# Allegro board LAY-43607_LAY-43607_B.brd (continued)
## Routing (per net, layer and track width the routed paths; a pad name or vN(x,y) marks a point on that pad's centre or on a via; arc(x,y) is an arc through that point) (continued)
QSG3_MDI3_N: length 55
  TOP w0.105: U123.D32 v2(40.94,79.95)
  L3_INT_1 w0.094: P2.2 35.29,107.25 35.54,106.99 36.89,106.99 37.85,106.03 37.85,105.67 37.94,105.57 37.95,105.57 38.04,105.48 38.04,105.29 37.95,105.2 37.94,105.2 37.85,105.1 37.85,104.91 37.94,104.82 37.95,104.82 38.04,104.73 38.04,104.54 37.95,104.44 37.94,104.44 37.85,104.35 37.85,102.45 37.3,101.9 27.31,101.9 22.99,97.58 22.99,89.73 26.33,86.39 33.21,86.39 39.65,79.95 v2(40.94,79.95)
QSG3_MDI3_P: length 55
  TOP w0.105: v2(39.07,78.77) 39.01,78.84 39.01,79.18 38.97,79.22 38.97,79.4 39.29,79.71 39.32,79.71 39.55,79.95 U123.D33
  L3_INT_1 w0.094: v2(39.07,78.77) 39.02,78.82 39.02,80.05 33.06,86.02 26.17,86.02 22.62,89.58 22.62,97.73 27.15,102.27 37.14,102.27 37.48,102.6 37.48,105.86 36.72,106.62 36.01,106.62 35.67,106.28 35.67,105.98 P2.8
QSGM_REXT: length 4.5
  TOP w0.137: R662.1 41.64,85.74 41.83,85.54 41.83,84.07 41.97,83.94 U123.A8
QSGM_REXT0: length 3.5
  TOP w0.137: U123.D17 46,70.19 46,69.69 R663.1
QSGM_REXT1: length 3.6
  TOP w0.137: R663.2 46.65,70.54 45.25,71.95 U123.D18
QSGPHY1_INT_B: length 66.7
  TOP w0.137: v3(71.82,44.59) 71.42,44.99 U14.F15 ; v2(31.84,71.21) R660.2
  L3_INT_1 w0.107: v2(61.81,67.38) 61.81,67.37 59.02,67.37 57.42,68.98 55.33,68.98 54.81,69.5 51.74,69.5 51.22,70.02 44.91,70.02 44.41,69.52 43.88,69.52 43.83,69.5 43.75,69.48 42.78,69.48 42.7,69.5 42.65,69.52 41.93,69.52 41.53,69.92 33.13,69.92 v2(31.84,71.21)
  BOTTOM w0.137: v2(61.81,67.38) 63.6,67.38 64.15,66.82 64.15,61.94 64.55,61.55 64.55,59.88 63.95,59.28 63.95,56.19 64.49,55.66 64.49,46.03 65.06,45.46 71.33,45.46 71.82,44.97 v3(71.82,44.59) ; R660.2 v2(31.84,71.21)
QSGPHY1_RST_B: length 26.6
  TOP w0.105: 35.85,74.97 U123.B5
  TOP w0.137: 35.85,74.97 34.93,74.97 R654.1 33.86,76.58 v2(33.69,76.75)
  BOTTOM w0.137: U62.4 47.04,65.52 46.84,65.72 46.84,67.66 44.58,69.92 35.77,69.92 34.93,70.75 34.93,75.51 v2(33.69,76.75)
QSGPHY_REFCLK_125M_N: length 30.3
  TOP w0.124: C850.1 38.79,67.58 38.79,67.18 38.26,66.65 37.7,66.65 34.67,69.68 31.92,69.68 30.65,70.96 20.88,70.96 19.53,69.6 19.53,67.31 20.58,66.26 20.83,66.26 20.95,66.39 20.95,66.39 21.08,66.51 21.33,66.51 21.45,66.39 21.45,66.39 21.57,66.26 21.82,66.26 21.95,66.39 21.95,66.39 22.07,66.51 22.32,66.51 22.45,66.39 22.45,66.39 22.57,66.26 23.99,66.26 U50.13
QSGPHY_REFCLK_125M_P: length 30.4
  TOP w0.124: U50.14 23.97,65.94 20.44,65.94 19.21,67.18 19.21,69.73 20.75,71.28 30.78,71.28 32.05,70 34.8,70 37.83,66.97 38.13,66.97 38.47,67.31 38.47,67.58 C849.1
QSPI_A_CS0: length 62.8
  TOP w0.137: U532.7 v2(105.78,25.44) 107.33,26.99 109.38,26.99 110.5,28.11 v2(110.5,29.05) ; v3(74.2,50.96) 73.83,50.96 73.83,50.96 73.39,50.96 73.29,50.86 73.29,50.86 U14.D8
  L3_INT_1 w0.107: v3(74.2,50.96) 80.43,50.96 80.65,50.74 81.47,50.74 84.64,47.57 86.99,47.57 87.22,47.35 90.94,47.35 92.35,45.93 94.48,45.93 95.92,44.5 95.92,42.95 97.27,41.6 98.79,41.6 102.93,37.46 104,37.46 105.12,36.34 105.12,34.76 106.13,33.75 106.13,33 106.39,32.75 106.39,30.42 107.76,29.05 v2(110.5,29.05)
  BOTTOM w0.137: R809.2 105.1,25.16 105.38,25.44 v2(105.78,25.44)
QSPI_A_DATA0: length 59.3
  TOP w0.137: U14.D11 73.03,48.2 v3(73.43,48.59) ; v2(109.43,27.63) 109.89,28.08 109.89,30.09 111.6,31.79 U532.15
  L3_INT_1 w0.107: v2(109.43,27.63) 108.02,27.63 105.56,30.08 105.56,32.29 102.47,35.38 102.21,35.38 99.58,38.01 99.48,38.01 98.08,39.41 97.95,39.41 97.67,39.69 97.67,40 95.1,42.58 95.1,44.15 94.12,45.12 92,45.12 90.6,46.52 86.88,46.52 86.65,46.75 84.37,46.75 81.26,49.87 80.27,49.87 79.68,49.28 79.21,49.28 79.1,49.38 79.1,49.8 79,49.9 78.78,49.9 78.68,49.8 78.68,49.08 78.55,48.95 77.02,48.95 76.92,49.06 76.92,49.81 76.81,49.92 76.6,49.92 76.49,49.81 76.49,49.06 76.38,48.95 76.17,48.95 76.06,49.06 76.06,49.81 75.96,49.92 75.74,49.92 75.64,49.81 75.64,49.06 75.53,48.95 74.38,48.95 74.37,48.95 74.08,48.95 74.08,48.95 73.78,48.95 v3(73.43,48.59)
QSPI_A_DATA1: length 59.5
  TOP w0.137: v2(109.28,25.98) 107.82,24.51 107.24,24.51 106.9,24.17 U532.8 ; U14.C12 v3(74.22,47.8)
  L3_INT_1 w0.107: v2(109.28,25.98) 109.28,26.75 108.67,27.37 107.69,27.37 104.15,30.91 104.15,32.07 100.03,36.19 99.78,36.19 97.85,38.12 97.7,38.12 97.29,37.72 97.14,37.72 96.99,37.87 96.99,38.02 97.39,38.42 97.39,38.57 96.98,38.98 96.8,38.98 95.74,40.04 95.74,41.35 94.68,42.41 94.68,43.6 94.13,44.16 93.98,44.16 92.99,43.17 92.83,43.17 92.68,43.32 92.68,43.47 93.64,44.43 93.64,44.64 93.48,44.81 93.1,44.81 92.68,44.39 92.15,44.39 90.43,46.11 86.71,46.11 86.54,46.28 84.36,46.28 82.25,48.4 80.61,48.4 80.13,47.93 74.71,47.93 74.58,47.8 v3(74.22,47.8)
QSPI_A_DATA2: length 60.8
  TOP w0.137: R810.2 U532.9 110.68,24.17 v2(109.88,23.37) ; U14.D13 73.42,46.99 v3(73.43,46.99)
  L3_INT_1 w0.107: v3(73.43,46.99) 73.83,47.4 74.33,47.4 74.44,47.5 82.71,47.5 84.26,45.95 84.26,45.63 84.53,45.35 85.89,45.35 85.99,45.46 85.99,45.61 86.1,45.72 86.31,45.72 86.42,45.61 86.42,45.46 86.53,45.35 87.25,45.35 87.36,45.46 87.36,45.63 87.46,45.74 87.68,45.74 87.78,45.63 87.78,45.46 87.89,45.35 88.1,45.35 88.21,45.46 88.21,45.63 88.32,45.74 88.53,45.74 88.64,45.63 88.64,45.46 88.74,45.35 89.89,45.35 93.16,42.09 93.31,42.09 93.67,42.45 93.82,42.45 93.97,42.3 93.97,42.15 93.61,41.79 93.61,41.64 95.82,39.43 95.82,37.23 96.43,36.62 98.06,36.62 98.22,36.45 98.37,36.45 98.52,36.6 98.67,36.6 98.82,36.45 98.82,36.3 98.68,36.15 98.68,36 99.5,35.17 100.47,35.17 102.29,33.35 102.29,33.2 102.03,32.93 102.03,32.78 102.18,32.63 102.33,32.63 102.6,32.89 102.75,32.89 102.9,32.74 102.9,32.59 102.63,32.33 102.63,32.18 102.79,32.03 102.94,32.03 103.2,32.29 103.35,32.29 103.64,32 103.64,30.94 107.54,27.04 108.54,27.04 108.85,26.73 108.85,25.73 109.88,24.7 v2(109.88,23.37)
QSPI_A_DATA3: length 60.3
  TOP w0.137: v2(101.41,33.4) 101.74,33.06 U532.1 ; v3(74.23,46.99) 74.22,46.99 U14.C13
  L3_INT_1 w0.107: v2(101.41,33.4) 101.12,33.69 101.12,34.08 100.38,34.82 99.93,34.82 99.83,34.72 99.83,34.63 99.72,34.52 99.51,34.52 99.4,34.63 99.4,34.72 99.29,34.82 99.08,34.82 98.97,34.72 98.97,34.63 98.87,34.52 98.65,34.52 98.55,34.63 98.55,34.72 98.44,34.82 98.2,34.82 96.82,36.2 96.42,36.2 95.97,35.75 95.74,35.75 95.63,35.86 95.63,36.09 95.53,36.2 95.31,36.2 95.21,36.09 95.21,35.86 95.1,35.75 94.89,35.75 94.78,35.86 94.78,36.09 94.67,36.2 94.46,36.2 94.35,36.09 94.35,35.86 94.25,35.75 93.83,35.75 93.49,36.1 93.49,36.42 93.66,36.59 95.22,36.59 95.32,36.69 95.32,38.06 95.22,38.17 93.7,38.17 93.59,38.28 93.59,38.49 93.7,38.6 95.22,38.6 95.32,38.7 95.32,39.34 95.08,39.59 94.93,39.59 94.37,39.03 94.16,39.03 94.05,39.13 94.05,39.33 94.62,39.9 94.62,40.05 94.47,40.19 94.32,40.19 93.87,39.74 93.72,39.74 93.61,39.85 93.61,40.08 94.02,40.49 94.02,40.64 90.32,44.34 89.98,44.34 89.88,44.24 89.88,43.97 89.77,43.86 89.56,43.86 89.45,43.97 89.45,44.92 89.34,45.03 89.15,45.03 89.02,44.9 89.02,43.97 88.92,43.86 88.7,43.86 88.6,43.97 88.6,44.24 88.49,44.34 88.28,44.34 88.17,44.24 88.17,43.97 88.06,43.86 87.85,43.86 87.74,43.97 87.74,44.24 87.64,44.34 87.4,44.34 87.3,44.45 87.3,44.94 87.19,45.04 86.98,45.04 86.87,44.94 86.87,44.45 86.76,44.34 86.55,44.34 86.44,44.45 86.44,44.94 86.34,45.04 86.12,45.04 86.02,44.94 86.02,44.45 85.74,44.17 85.13,44.17 85.02,44.28 85.02,44.38 84.92,44.49 84.7,44.49 84.5,44.28 84.35,44.28 83.96,44.66 83.96,44.81 84.22,45.08 84.22,45.23 83.95,45.5 83.95,45.82 83.78,45.99 83.63,45.99 83.22,45.58 83.07,45.58 82.92,45.73 82.92,45.88 83.04,46 83.04,46.15 82.9,46.28 82.9,46.69 82.67,46.92 82.67,46.95 82.43,47.19 75.94,47.19 75,46.25 74.67,46.25 74.48,46.44 74.48,46.74 v3(74.23,46.99)
  BOTTOM w0.137: v2(101.41,33.4) 101.74,33.06 102.01,33.06 102.16,32.91 R811.2
QSPI_A_SCK: length 59.7
  TOP w0.137: U532.16 111.57,33.06 109.41,30.9 v2(109.41,28.57) ; v3(74.23,50.19) 73.83,49.8 U14.C9
  L3_INT_1 w0.107: v3(74.23,50.19) 74.62,50.59 80.36,50.59 80.56,50.4 81.26,50.4 82.12,49.53 82.14,49.53 84.51,47.16 86.82,47.16 87.05,46.94 90.74,46.94 92.23,45.45 94.38,45.45 95.51,44.32 95.51,42.75 97.12,41.14 97.73,41.14 101.28,37.59 101.71,37.59 102.93,36.37 103.31,36.37 104.05,35.63 104.05,34.46 105.97,32.53 105.97,30.25 108.12,28.11 109.56,28.11 109.83,27.84 109.83,26.74 109.98,26.6 110.4,26.6 110.53,26.73 110.53,28.05 110.02,28.57 v2(109.41,28.57)
R_LED_ASLEEP: length 5.2
  TOP w0.137: R191.1 94.09,47.21 Q4.3
R_USB1_LED: length 1.2
  TOP w0.137: R244.2 114.2,99.33 D4.A
R_USB2_LED: length 1.4
  TOP w0.137: D508.A 107.29,99.06 107.26,99.03 106.54,99.03
RESET_MCU_B: length 66.4
  TOP w0.137: R939.2 79.33,83.3 79.48,83.45 86.07,83.45 v2(86.37,83.15)
  L3_INT_1 w0.107: v2(97.05,73.03) 95.09,73.03 94.05,71.99 84.35,71.99 82.12,69.76 76.08,69.76 75.71,70.14 70.87,70.14 v2(69.89,69.16) ; v2(98.53,77.35) 91.45,77.35 86.37,82.43 v2(86.37,83.15)
  BOTTOM w0.137: U547.2 100.01,67.45 100.01,68.65 99.5,69.16 98.42,69.16 97.05,70.53 v2(97.05,73.03) 97.05,73.55 98.3,74.8 98.3,76.01 98.53,76.24 v2(98.53,77.35) ; R938.2 v2(69.89,69.16)
RESET_REQ_B: length 38.1
  TOP w0.137: R298.2 120.89,16.86 v2(120.89,17.72) ; v2(130.57,18.58) 131.17,19.19 131.17,37.96 131.4,38.2 131.4,41.73 J14.1
  BOTTOM w0.137: v2(120.89,17.72) U534.2 120.89,16.12 125.43,16.12 127.59,18.28 130.26,18.28 v2(130.57,18.58)
RST_I2CMUX_B: length 7.6
  TOP w0.137: v2(87.94,84.65) 87.94,84.69 88.22,84.97 U525.3
  BOTTOM w0.137: v2(87.94,84.65) 87.86,84.73 R758.2 87.35,85.56 86.28,86.63 86.28,87.51 v2(87.41,88.64) U527.4
RST_MEM_B: length 111.1
  TOP w0.137: U15.P1 89.35,7.42 88.63,7.42 86.89,5.67 v2(86.89,5.64)
  L3_INT_1 w0.107: v2(86.89,5.64) 87.55,4.98 89.33,4.98 90.09,5.74 91.06,5.74 91.08,5.72 97.09,5.72 101.71,10.35 v2(101.71,17.59) ; v1(78.16,7.71) 77.78,7.32 71.32,7.32 70.9,7.75 69.19,7.75 68.77,7.32 68.12,7.32 67.86,7.58 67.86,7.87 67.64,8.09 67.06,8.09 v1(66.68,7.71) 66.22,7.25 66.22,5.99 64.36,4.13 58.91,4.13 57.5,5.55 57.5,5.66 57.11,6.04 56.87,6.04 v1(55.2,7.71) 54.82,8.09 44.1,8.09 v1(43.72,7.71) ; v2(115.97,26.36) v2(115.97,16.44)
  L4_INT_2 w0.107: v1(78.16,7.71) 78.16,6.67 78.55,6.29 78.55,5.98 79.23,5.3 81.48,5.3 82.28,6.11 84.02,6.11 84.4,6.49 84.83,6.49 85.8,5.53 86.77,5.53 v2(86.89,5.64)
  BOTTOM w0.137: v2(115.97,16.44) 115.55,16.02 R558.2 103.69,17.59 v2(101.71,17.59) ; U114.4 121.72,26.41 121.19,26.93 119.76,26.93 119.2,26.36 v2(115.97,26.36)
RSV_IO: length 9.2
  TOP w0.137: R824.1 52.33,62.01 52.33,58.86 v2(53.22,57.96) ; U14.AF3 v2(55.02,55)
  L4_INT_2 w0.107: v2(53.22,57.96) 53.22,56.8 v2(55.02,55)
SCAN_MODE: length 20.3
  TOP w0.137: v3(69.42,41.4) U14.H19
  BOTTOM w0.137: v3(69.42,41.4) 69.02,41.79 69.02,44.76 69.26,45 71.15,45 71.4,44.75 71.4,44.49 71.67,44.22 71.98,44.22 73.07,45.31 75.32,45.31 76.55,44.08 76.55,44.08 77.08,43.55 81.55,43.55 R160.2
SD1_IMP_CAL_RX: length 2.3
  TOP w0.137: v2(59.82,48.6) U14.Y11
  BOTTOM w0.137: v2(59.82,48.6) 59.43,48.99 59.43,49.69 R260.1
SD1_IMP_CAL_TX: length 16.4
  TOP w0.137: v2(59.02,52.6) U14.AA6 ; v2(46.34,54.39) R258.1
  L3_INT_1 w0.107: v2(46.34,54.39) 47.75,54.39 48.8,55.44 51.63,55.44 54.06,53.01 56.78,53.01 57.04,53.27 57.04,53.55 57.26,53.78 57.98,53.78 59.02,52.74 v2(59.02,52.6)
SD1_REFCLK2_N: length 40.6
  TOP w0.124: R792.2 24.33,60.17 24.59,59.91 24.59,59.55 24.77,59.38 24.77,59.2 24.69,59.13 24.69,58.95 24.87,58.78 25.05,58.78 25.12,58.85 25.29,58.85 26.23,57.91 35.43,57.91 36.65,56.69 38.2,56.69 40.01,58.5 40.29,58.5 v2(40.58,58.21) ; U14.AB8 v2(58.22,51)
  BOTTOM w0.124: v2(58.22,51) 58.17,51.05 55.57,51.05 53.18,53.43 48.87,53.43 47.12,55.18 45.1,55.18 41.78,58.5 40.87,58.5 v2(40.58,58.21)
SD1_REFCLK2_P: length 40.6
  TOP w0.124: U14.AA8 v2(59.02,51) ; v2(40.58,59.12) 40.28,58.82 39.87,58.82 38.07,57.01 36.78,57.01 35.56,58.23 26.36,58.23 24.91,59.69 24.91,59.91 R791.2
  BOTTOM w0.124: v2(59.02,51) 58.78,51 58.39,51.39 58.06,51.39 58.04,51.37 55.7,51.37 53.31,53.75 49,53.75 47.26,55.5 45.23,55.5 41.91,58.82 40.87,58.82 v2(40.58,59.12)
SD1_RX2_N: length 25.6
  TOP w0.124: C1583.1 42.09,48.77 40.93,48.77 40.26,49.44 40.26,54.86 41.53,56.13 41.53,60.17 41.16,60.54 41.16,71.6 arc(41.12,71.77) 41.03,71.91 U123.D13
SD1_RX2_P: length 25.6
  TOP w0.124: C1582.1 42.09,49.09 41.07,49.09 40.58,49.57 40.58,54.73 41.85,55.99 41.85,60.3 41.48,60.67 41.48,69.39 arc(41.5,69.46) 41.57,69.49 arc(41.64,69.52) 41.67,69.59 41.67,69.9 arc(41.64,69.97) 41.57,70 arc(41.5,70.02) 41.48,70.09 41.48,70.4 arc(41.5,70.47) 41.57,70.5 arc(41.65,70.53) 41.69,70.61 41.69,70.89 arc(41.65,70.97) 41.57,71.01 arc(41.5,71.04) 41.48,71.1 41.48,71.6 arc(41.51,71.77) 41.61,71.91 U123.D14
SD1_TX2_N: length 34.4
  TOP w0.124: U14.AE10 v2(55.82,48.6)
  BOTTOM w0.124: v1(42.82,68.88) 42.99,68.88 arc(43.07,68.84) 43.11,68.77 43.11,67.62 arc(42.93,67.18) 42.49,67 41.72,67 arc(41.43,66.94) 41.18,66.78 39.85,65.44 arc(39.62,65.1) 39.54,64.7 39.54,58.29 arc(39.61,57.93) 39.82,57.62 44.64,52.79 arc(45.63,52.13) 46.79,51.9 49.95,51.9 arc(50.37,51.82) 50.73,51.58 52.61,49.69 arc(53.07,49.39) 53.61,49.28 55.87,49.28 arc(56.01,49.22) 56.06,49.08 56.06,48.94 arc(56.05,48.84) 55.99,48.76 v2(55.82,48.6)
SD1_TX2_P: length 34.4
  TOP w0.124: U14.AD10 v2(56.62,48.6)
  BOTTOM w0.124: v2(56.62,48.6) 56.46,48.76 arc(56.4,48.84) 56.38,48.94 56.38,49.08 arc(56.23,49.45) 55.87,49.6 53.61,49.6 arc(53.19,49.68) 52.84,49.92 50.95,51.81 arc(50.49,52.11) 49.95,52.22 46.79,52.22 arc(45.75,52.43) 44.87,53.02 40.04,57.84 arc(39.91,58.05) 39.86,58.29 39.86,64.7 arc(39.91,64.98) 40.07,65.21 41.41,66.55 arc(41.55,66.65) 41.72,66.68 42.49,66.68 arc(43.15,66.95) 43.43,67.62 43.43,68.75 arc(43.46,68.84) 43.55,68.88 v1(43.71,68.88)
SD2_IMP_CAL_RX: length 4.8
  TOP w0.137: v2(59.82,47.8) U14.Y12
  BOTTOM w0.137: R261.1 61.64,45.43 61.83,45.62 61.83,47.16 61.6,47.39 60.23,47.39 v2(59.82,47.8)
SD2_IMP_CAL_TX: length 25.7
  TOP w0.137: R259.1 v2(44.56,48.38) ; v2(59.82,40.6) U14.Y20
  L3_INT_1 w0.107: v2(44.56,48.38) 43.74,47.56 43.74,44.84 44.56,44.02 44.56,41.61 46.79,39.39 59.16,39.39 59.44,39.67 59.44,39.95 59.82,40.34 v2(59.82,40.6)
SD2_REFCLK1_N: length 36.3
  TOP w0.124: v2(33.93,65.71) 33.66,65.98 32.92,65.98 R784.2 ; U14.AE13 v2(55.82,47)
  BOTTOM w0.124: v2(55.82,47) 55.75,47.07 55.41,47.07 arc(55.34,47.04) 55.3,46.97 arc(55.25,46.9) 55.18,46.88 54.91,46.88 arc(54.84,46.9) 54.79,46.97 arc(54.75,47.04) 54.68,47.07 52.83,47.07 50.82,49.08 50.82,50.07 50.24,50.65 45.09,50.65 37.63,58.11 37.63,58.22 37.63,62.83 35.37,65.09 35.19,65.09 35.01,64.91 34.83,64.91 34.66,65.09 34.66,65.26 34.84,65.44 34.84,65.62 34.45,66.01 34.22,66.01 v2(33.93,65.71)
SD2_REFCLK1_P: length 36.3
  TOP w0.124: v2(33.93,66.62) 33.6,66.3 32.77,66.3 R783.2 ; U14.AD13 v2(56.62,47)
  BOTTOM w0.124: v2(56.62,47) 56.23,47.39 52.97,47.39 51.14,49.21 51.14,50.2 50.37,50.97 45.22,50.97 37.95,58.24 37.95,58.36 37.95,62.97 34.59,66.33 34.22,66.33 v2(33.93,66.62)
SD2_REFCLK2_N: length 41
  TOP w0.124: v2(36.07,59.94) 36.25,60.12 36.25,61.4 35.61,62.04 34.13,62.04 R790.2
  TOP w0.137: v3(58.22,42.2) U14.AB19
  L4_INT_2 w0.094: v2(36.88,52.49) 36.71,52.66 36.4,52.66 36.09,52.97 36.09,54.12 36.21,54.23 36.21,59.8 v2(36.07,59.94)
  BOTTOM w0.124: v3(58.22,42.2) 57.98,42.44 57.74,42.44 57.59,42.59 55.99,42.59 55.19,43.39 50.34,43.39 49.64,42.68 44.45,42.68 38.87,48.26 38.87,51.25 37.5,52.62 37.01,52.62 v2(36.88,52.49)
SD2_REFCLK2_P: length 41
  TOP w0.124: R789.2 34.13,62.36 35.74,62.36 36.57,61.54 36.57,60.09 v2(36.78,59.88)
  TOP w0.137: v3(58.22,43) U14.AB18
  L4_INT_2 w0.094: v2(36.78,59.88) 36.58,59.68 36.58,54.38 36.58,54.08 36.46,53.96 36.46,53.13 36.56,53.03 36.71,53.03 v2(36.88,53.2)
  BOTTOM w0.124: v3(58.22,43) 57.98,42.76 57.87,42.76 57.72,42.91 56.12,42.91 55.32,43.71 50.21,43.71 49.5,43 44.58,43 39.19,48.4 39.19,51.39 37.63,52.94 37.14,52.94 v2(36.88,53.2)
SD2_RX1_N: length 41.9
  TOP w0.124: v2(23.02,55.79) 23.05,55.82 arc(23.16,55.99) 23.2,56.18 23.2,56.3 arc(23.43,56.87) 24,57.1 24.34,57.1 arc(24.4,57.13) 24.43,57.19 arc(24.45,57.25) 24.51,57.28 24.84,57.28 arc(24.9,57.25) 24.92,57.19 arc(24.95,57.13) 25.01,57.1 25.33,57.1 arc(25.4,57.13) 25.42,57.19 arc(25.45,57.25) 25.51,57.28 25.83,57.28 arc(25.89,57.25) 25.92,57.19 arc(25.94,57.13) 26.01,57.1 32.82,57.1 arc(35.88,56.18) 37.85,53.67 39.59,49.07 arc(39.72,48.58) 39.77,48.08 39.77,47.85 arc(39.96,46.87) 40.51,46.05 42.95,43.61 arc(43.72,43.09) 44.63,42.91 50.13,42.91 50.3,42.91 arc(50.42,42.94) 50.53,43.01 50.69,43.17 arc(51.98,44.03) 53.5,44.33 arc(53.68,44.3) U14.AH16
  BOTTOM w0.124: J46.43 23.13,55.53 arc(23.11,55.67) v2(23.02,55.79)
SD2_RX1_P: length 42
  TOP w0.124: v2(23.75,55.79) 23.63,55.9 arc(23.55,56.03) 23.52,56.18 23.52,56.3 arc(23.66,56.64) 24,56.78 32.82,56.78 arc(35.7,55.92) 37.55,53.56 39.29,48.96 arc(39.41,48.53) 39.45,48.08 39.45,47.85 arc(39.67,46.75) 40.29,45.82 42.73,43.38 arc(43.6,42.8) 44.63,42.59 50.3,42.59 arc(50.55,42.64) 50.75,42.78 50.91,42.94 arc(52.02,43.68) 53.32,43.94 arc(53.49,43.91) 53.63,43.81 arc(53.68,43.78) 53.75,43.76 54.14,43.76 arc(54.2,43.77) 54.26,43.79 arc(54.48,43.95) U14.AG16
  BOTTOM w0.124: J46.41 23.63,55.53 arc(23.66,55.67) v2(23.75,55.79)
SD2_RX3_N: length 33
  TOP w0.124: J52.43 arc(25.82,42.53) 25.8,42.65 25.8,44.12 arc(26.06,44.74) 26.68,44.99 26.93,44.99 arc(27.05,44.95) 27.1,44.83 arc(27.14,44.71) 27.26,44.66 27.43,44.66 arc(27.55,44.71) 27.59,44.83 arc(27.64,44.95) 27.76,44.99 27.93,44.99 arc(28.04,44.95) 28.09,44.83 arc(28.14,44.71) 28.26,44.66 28.42,44.66 arc(28.54,44.71) 28.59,44.83 arc(28.64,44.95) 28.76,44.99 28.92,44.99 arc(29.04,44.95) 29.09,44.83 arc(29.14,44.71) 29.25,44.66 29.42,44.66 arc(29.54,44.71) 29.59,44.83 arc(29.63,44.95) 29.75,44.99 29.92,44.99 arc(30.03,44.95) 30.08,44.83 arc(30.13,44.71) 30.25,44.66 30.41,44.66 arc(30.53,44.71) 30.58,44.83 arc(30.63,44.95) 30.75,44.99 31.23,44.99 arc(31.31,44.98) 31.37,44.93 31.92,44.39 arc(32.29,44.14) 32.74,44.05 34.97,44.05 arc(35.8,43.89) 36.5,43.42 37.53,42.38 arc(38.45,41.77) 39.54,41.55 50.41,41.55 arc(50.67,41.6) 50.89,41.73 arc(51.16,41.84) 51.44,41.88 53.62,41.88 arc(53.73,41.86) U14.AH19
SD2_RX3_P: length 33.1
  TOP w0.124: U14.AG19 54.62,41.94 arc(54.54,42.14) 54.34,42.22 51.5,42.22 arc(51.08,42.16) 50.7,41.99 arc(50.69,41.98) 50.68,41.97 arc(50.55,41.9) 50.41,41.87 39.54,41.87 arc(38.58,42.06) 37.76,42.61 36.72,43.64 arc(35.92,44.18) 34.97,44.37 32.74,44.37 arc(32.42,44.44) 32.14,44.62 31.6,45.16 arc(31.43,45.27) 31.23,45.31 26.68,45.31 arc(25.83,44.96) 25.48,44.12 25.48,42.65 arc(25.46,42.53) J52.41
SD2_TX1_N: length 39.7
  BOTTOM w0.124: C1168.2 24.56,57.7 arc(24.68,57.89) 24.73,58.11 24.73,58.46 arc(24.9,58.87) 25.31,59.04 25.56,59.04 arc(25.65,59.08) 25.69,59.17 arc(25.73,59.26) 25.82,59.3 26.06,59.3 arc(26.15,59.26) 26.19,59.17 arc(26.23,59.08) 26.32,59.04 26.56,59.04 arc(26.65,59.08) 26.69,59.17 arc(26.72,59.26) 26.82,59.3 27.06,59.3 arc(27.15,59.26) 27.18,59.17 arc(27.22,59.08) 27.31,59.04 27.65,59.04 arc(28.52,58.87) 29.26,58.38 arc(29.51,58.21) 29.8,58.15 32.17,58.15 arc(33.55,57.9) 34.73,57.15 39.47,52.62 arc(40.74,51.17) 41.75,49.53 42.9,47.25 arc(43.88,45.92) 45.24,44.99 arc(46.3,44.64) 47.41,44.52 55.59,44.52 arc(55.88,44.46) 56.13,44.29 v1(56.22,44.2)
SD2_TX1_P: length 39.6
  BOTTOM w0.124: C1166.2 25.22,57.7 arc(25.09,57.89) 25.05,58.11 25.05,58.46 arc(25.12,58.65) 25.31,58.72 27.65,58.72 arc(28.4,58.57) 29.03,58.15 arc(29.38,57.92) 29.8,57.83 32.17,57.83 arc(33.43,57.6) 34.51,56.92 39.25,52.39 arc(40.49,50.98) 41.47,49.38 42.61,47.11 arc(43.65,45.69) 45.11,44.7 arc(46.23,44.32) 47.41,44.2 55.43,44.2 arc(55.61,44.17) 55.79,44.11 arc(55.84,44.07) 55.87,44.02 arc(55.9,43.97) 55.94,43.93 arc(56.08,43.82) 56.26,43.79 56.5,43.79 arc(56.61,43.81) 56.7,43.87 v1(57.02,44.2)
SD2_TX3_N: length 34.9
  BOTTOM w0.124: v1(24.51,44.63) 24.47,44.68 arc(24.36,44.83) 24.33,45.01 arc(24.34,45.06) 24.35,45.11 arc(24.39,45.19) 24.47,45.22 25.71,45.22 arc(25.85,45.16) 25.9,45.02 arc(25.96,44.88) 26.1,44.83 26.21,44.83 arc(26.35,44.88) 26.4,45.02 arc(26.46,45.16) 26.6,45.22 26.71,45.22 arc(26.84,45.16) 26.9,45.02 arc(26.96,44.88) 27.1,44.83 27.2,44.83 arc(27.34,44.88) 27.4,45.02 arc(27.46,45.16) 27.59,45.22 27.7,45.22 arc(27.84,45.16) 27.9,45.02 arc(27.95,44.88) 28.09,44.83 28.2,44.83 arc(28.34,44.88) 28.39,45.02 arc(28.45,45.16) 28.59,45.22 31.65,45.22 arc(32.19,45.11) 32.64,44.81 33.49,43.96 arc(33.61,43.85) 33.73,43.74 arc(33.78,43.71) 33.83,43.68 34.39,43.12 arc(36.29,42.18) 38.37,41.8 38.37,41.8 55.55,41.8 arc(55.89,41.8) v1(56.22,41.8)
SD2_TX3_P: length 35
  BOTTOM w0.124: v1(23.77,44.63) arc(23.91,44.82) 24,45.04 24.02,45.1 arc(24.02,45.1) 24.02,45.1 arc(24.03,45.13) 24.03,45.15 arc(24.18,45.43) 24.47,45.54 31.65,45.54 arc(32.31,45.41) 32.86,45.04 33.72,44.18 arc(33.82,44.09) 33.93,44 arc(33.95,43.98) 33.98,43.97 arc(34.02,43.94) 34.06,43.91 34.6,43.37 arc(36.4,42.48) 38.38,42.12 arc(38.44,42.12) 38.51,42.12 55.88,42.12 55.89,42.13 55.91,42.13 55.92,42.13 55.95,42.14 56.05,42.15 56.07,42.16 56.11,42.17 arc(56.28,42.18) 56.43,42.13 arc(56.48,42.1) 56.53,42.09 arc(56.8,41.97) v1(57.02,41.8)
SD_CLK: length 81.8
  TOP w0.137: R832.2 79.13,110.46 79.62,109.97 v2(79.73,109.97) U39.1 ; v2(64.89,59.61) 64.89,60.04 64.74,60.19 64.74,68.93 65.02,69.21 65.02,70.53 64.89,70.66 v2(64.89,71.22)
  L3_INT_1 w0.107: v2(64.89,71.22) 59.72,71.22 57.34,73.59 57.34,86.1 60.02,88.78 61.9,88.78 63.04,89.91 63.04,93.2 64.31,94.47 64.31,97.06 68.03,100.78 70.55,100.78 v2(79.73,109.97)
  BOTTOM w0.137: v2(79.73,109.97) 77.8,111.89 J55.5 ; R239.2 65.26,59.24 v2(64.89,59.61)
SD_CMD: length 85.6
  TOP w0.137: U14.P2 65.46,55.83 65.46,58.44 64.4,59.5 64.4,69.07 64.68,69.35 64.68,70.39 v2(64.38,70.69) ; R833.2 77.94,110.35 v2(77.53,109.94) U38.4
  L3_INT_1 w0.107: v2(77.53,109.94) 76.29,109.94 75.48,109.13 75.48,108.67 69.87,103.07 68.64,103.07 66.74,101.16 66.74,100.08 63.9,97.24 63.9,94.64 62.62,93.37 62.62,90.09 61.62,89.09 59.89,89.09 57.03,86.23 57.03,83.29 55.94,82.2 55.94,74.56 59.65,70.85 64.17,70.85 64.33,70.69 v2(64.38,70.69)
  BOTTOM w0.137: v2(77.53,109.94) 78.04,109.43 79.94,109.43 80.22,109.71 80.22,112.51 80,112.72 J55.3
SD_DATA0: length 86.8
  TOP w0.137: v2(64.23,69.99) 64.23,69.38 63.92,69.07 63.92,59.36 65.02,58.25 U14.P1 ; R828.2 75.61,112.18 75.61,111.49 v2(75.61,111.48) 75.63,111.46 U38.7
  L3_INT_1 w0.107: v2(64.23,69.99) 59.63,69.99 56.35,73.27 54.84,73.27 54.15,73.96 54.15,82.29 54.67,82.81 54.67,83.83 55.01,84.17 55.95,84.17 56.32,84.54 56.32,86.39 59.82,89.89 60.55,89.89 61.8,91.14 61.8,93.71 63.07,94.99 63.07,97.58 65.92,100.42 65.92,105.37 68.54,107.99 70.16,107.99 71.68,109.52 74.73,109.52 75.09,109.88 75.09,110.76 74.68,111.17 74.68,112.39 74.9,112.62 75.39,112.62 75.61,112.39 v2(75.61,111.48)
  BOTTOM w0.137: v2(75.61,111.48) 75.61,111.91 75.61,111.91 75.61,112.07 75.6,112.08 J55.7
SD_DATA1: length 84.9
  TOP w0.137: U14.R2 63.78,55.83 63.78,57.62 61.93,59.47 61.93,64.49 62.67,65.22 62.67,67.12 62.12,67.67 62.12,68.72 62.73,69.33 62.73,69.51 v2(62.8,69.58) ; R829.2 74.64,110.25 v2(74.64,110) 74.7,109.94 U38.1
  L3_INT_1 w0.107: v2(74.64,110) 71.52,110 69.95,108.42 68.26,108.42 65.51,105.67 65.51,100.59 62.66,97.75 62.66,95.16 61.39,93.88 61.39,91.17 60.42,90.2 59.65,90.2 55.99,86.55 55.99,85.36 55.8,85.17 55.02,85.17 54.36,84.5 54.36,82.93 53.84,82.42 53.84,73.08 54.59,72.34 56.85,72.34 59.51,69.67 62.57,69.67 62.66,69.58 v2(62.8,69.58)
  BOTTOM w0.137: J55.8 74.5,110.56 74.64,110.42 v2(74.64,110)
SD_DATA2: length 85.9
  TOP w0.137: v2(63.98,71.64) 63.37,71.02 63.37,69.48 62.46,68.57 62.46,67.81 63.01,67.26 63.01,65.08 62.27,64.35 62.27,59.75 64.22,57.8 U14.R1 ; R830.2 82.76,110.46 v2(82.26,109.95) 82.24,109.97 U39.4
  L3_INT_1 w0.107: v2(82.26,109.95) 82.91,109.95 83.02,109.84 83.02,108.46 82.91,108.35 80.58,108.35 70.19,97.96 66.83,97.96 65.13,96.26 65.13,92.18 67.6,89.72 67.6,86.12 69.11,84.61 69.11,80.19 67.89,78.96 64.8,78.96 61.37,75.54 61.35,75.54 61.15,75.33 61.15,75.31 60.82,74.99 60.82,72.6 61.36,72.05 63.56,72.05 v2(63.98,71.64)
  BOTTOM w0.137: v2(82.26,109.95) 82.26,111.97 82.2,112.02 J55.1
SD_DATA3: length 85.6
  TOP w0.137: U14.T1 63.42,56.7 61.59,58.54 61.59,62.3 60.76,63.14 60.76,67.11 60.64,67.22 60.64,69.1 v2(63.17,71.63) ; R831.2 81.09,111.7 v2(81.29,111.5) 81.29,111.26 81.46,111.09 U39.5
  L3_INT_1 w0.107: v2(63.17,71.63) 60.98,71.63 60.18,72.44 60.18,74.19 57.65,76.71 57.65,85.97 60.15,88.47 62.06,88.47 63.45,89.86 63.45,93.03 64.72,94.3 64.72,96.89 68.2,100.37 71.13,100.37 80.24,109.48 80.24,113.39 80.35,113.5 81.13,113.5 81.29,113.33 v2(81.29,111.5)
  BOTTOM w0.137: J55.2 81.1,112.11 81.29,111.92 v2(81.29,111.5)
SDHC_CD_B: length 90
  TOP w0.137: R834.2 76.74,111.62 76.64,111.52 v2(76.64,111.47) 76.64,111.37 U38.5 ; v3(68.63,54.99) 68.62,54.99 U14.K3
  L3_INT_1 w0.107: v2(76.64,111.47) 76.64,110.78 71.74,105.88 68.59,105.88 66.33,103.62 66.33,100.25 63.49,97.41 63.49,94.82 62.21,93.54 62.21,91 60.71,89.5 59.87,89.5 56.63,86.26 56.63,83.83 55.56,82.76 55.14,82.76 54.49,82.11 54.49,74.07 54.97,73.58 56.47,73.58 59.66,70.4 v2(62.94,70.4)
  BOTTOM w0.137: v3(68.63,54.99) 68.63,55.13 69.05,55.56 69.05,56.23 70.38,57.56 70.38,57.56 71.08,58.26 71.08,67.24 69.33,68.99 69.33,69.61 66.91,72.03 64.99,72.03 63.37,70.4 v2(62.94,70.4) ; v2(76.64,111.47) 76.64,110.94 76.7,110.87 J55.9
SDHC_WP: length 5.5
  TOP w0.137: U14.L3 v3(66.99,54.17)
  BOTTOM w0.137: R241.1 65.83,56.56 65.83,54.86 66.07,54.62 66.54,54.62 v3(66.99,54.17)
SENSE_VDD: length 18.5
  TOP w0.254: v2(129.37,45.33) 129.37,45.29 129.04,44.96 128.78,44.96 R894.2 R899.2
  BOTTOM w0.254: R895.1 127.89,39.78 127.89,41.05 127.68,41.27 127.68,44.65 128.16,45.12 128.77,45.1 129.04,45.35 v2(129.37,45.33) 129.37,45.33 129.51,45.33 129.78,45.05 131.02,45.05 131.72,44.35 131.72,41.48 131.19,40.95 130.53,40.95 130.08,40.5 130.08,39.75 R893.1
SENSE_VSS: length 15.9
  TOP w0.254: v2(129.33,44.44) 129.19,44.58 128.75,44.58 R896.2
  BOTTOM w0.254: R897.1 129.7,39.77 129.7,40.66 130.37,41.33 131.03,41.33 131.34,41.64 131.34,44.19 130.86,44.67 129.76,44.67 129.53,44.44 v2(129.33,44.44) 129,44.45 128.76,44.72 128.31,44.74 128.06,44.49 128.06,41.42 128.27,41.21 128.27,39.78 R898.1
SI5332_SCL: length 2.7
  TOP w0.137: U50.11 23.5,67.34 R777.2
SI5332_SDA: length 2.5
  TOP w0.137: R778.2 23.21,66.84 U50.12
SLOT1_RST_B: length 12.8
  TOP w0.137: v2(20.88,48.38) 20.87,48.37 R666.2
  L3_INT_1 w0.107: v2(20.88,48.38) 17.48,51.78 v2(17.48,56.62)
  BOTTOM w0.137: v2(17.48,56.62) 17.45,56.64 U58.4 ; v2(20.88,48.38) J46.52
SLOT2_RST_B: length 41.8
  TOP w0.137: J52.52 v2(28.14,36.15)
  L3_INT_1 w0.107: v2(17.27,59.26) 15.95,57.94 15.95,47.94 27.73,36.15 v2(28.14,36.15) 28.87,35.43 30.99,35.43 33.95,38.39 35.69,38.39 v2(36.35,37.74)
  BOTTOM w0.137: U60.4 v2(17.27,59.26) ; R803.2 v2(36.35,37.74)
SOC_SD_CLK: length 1.3
  TOP w0.137: v3(65.42,54.99) U14.P3
  BOTTOM w0.137: R239.1 65.42,55.54 v3(65.42,54.99)
SPI_MISO: length 2.9
  TOP w0.137: R942.1 R941.1 76.19,102.08 U37.7
SW1LX: length 4.4
  TOP w0.254: 64.76,81.61 64.76,79.75 65.75,78.76 U561.5
SW2LX: length 4.3
  TOP w0.254: 63.14,79.54 64.15,78.53 65.41,78.53 65.67,78.26 U561.6
SW3LX: length 2.9
  TOP w0.254: 64.13,76.64 65.07,76.64 65.19,76.76 U561.9
SW5LX: length 2.5
  TOP w0.254: 76.82,75.48 76.82,75.62 76.18,76.26 U561.33
SW6LX: length 2.7
  TOP w0.254: 77.33,76.5 76.58,76.5 76.31,76.76 U561.34
SW7LX: length 3
  TOP w0.254: U561.36 77.2,77.76 77.58,78.15
SW_QSGPHY1_RST_B: length 20.3
  TOP w0.137: v2(50.12,63.51) 51.16,62.46 51.16,62.16 52.06,61.27 52.06,58.53 53.33,57.26 54.36,57.26 U14.AF1 ; R867.2 46.3,65.57 45.9,65.57 v2(44.56,64.22)
  L3_INT_1 w0.107: v2(50.12,63.51) 48.96,64.67 45,64.67 v2(44.56,64.22)
  BOTTOM w0.137: U62.1 v2(44.56,64.22)
SW_RST: length 29.6
  TOP w0.137: v2(129.37,18.79) 129.48,18.79 130.76,20.07 130.76,34.95 128.81,36.9 SW6.2
  BOTTOM w0.137: v2(129.37,18.79) 124.88,18.79 R299.2 U534.1
SW_SLOT1_RST_B: length 46.6
  TOP w0.137: v2(57.42,54.2) U14.AC4
  L3_INT_1 w0.107: v2(23.61,61.39) 24.54,62.32 30.14,62.32 30.62,61.84 31.49,61.84 34.79,58.54 38.76,58.54 42.24,55.06 47.84,55.06 48.53,55.75 51.92,55.75 52.72,54.95 52.72,54.95 53.86,53.81 56.81,53.81 57.19,54.2 v2(57.42,54.2)
  BOTTOM w0.137: U58.1 18.65,57.95 R865.2 20.26,57.44 20.97,57.44 23.19,59.66 23.19,60.98 v2(23.61,61.39)
SW_SLOT2_RST_B: length 52.4
  TOP w0.137: U14.AC1 57.82,56.57 v2(57.67,56.72)
  L3_INT_1 w0.107: v2(18.69,64.67) 18.98,64.96 20.23,64.96 21.67,66.4 27.85,66.4 29.33,64.91 30.42,64.91 32.44,62.9 34.21,62.9 36.81,60.3 41.35,60.3 43.04,58.61 45.58,58.61 46.4,57.8 48.16,57.8 48.41,58.05 52.52,58.05 53.02,57.55 56,57.55 56.9,58.46 v2(56.9,58.52)
  L4_INT_2 w0.107: v2(57.67,56.72) 57.67,57.1 57.67,57.11 57.67,57.76 v2(56.9,58.52)
  BOTTOM w0.137: R866.2 19.95,59.86 19.24,60.56 U60.1 v2(18.69,64.67)
SW_UBUS1_RST: length 19.6
  TOP w0.137: R868.2 44.76,62.52 v2(44.66,62.62) ; v2(53.24,61.78) 52.94,61.48 52.94,58.92 54.34,57.52 54.66,57.52 55.8,56.38 55.8,55.82 U14.AE2
  L3_INT_1 w0.107: v2(44.66,62.62) 44.99,62.95 47.35,62.95 48.81,61.49 52.95,61.49 v2(53.24,61.78)
  BOTTOM w0.137: v2(44.66,62.62) 45.08,62.62 45.18,62.52 U546.1
SYS_CLK_100MHZ_LVCMOS: length 108.3
  TOP w0.137: U14.G14 71.05,45.37 76.35,45.37 77.91,46.93 82.2,46.93 82.79,47.52 85.17,47.52 85.65,47.99 85.65,51.97 83.28,54.34 83.16,54.34 82.91,54.59 82.91,56.04 82.67,56.28 82.67,61.18 85.54,64.04 85.54,64.14 89.53,68.13 89.63,68.13 92.08,70.58 v2(92.74,70.58) ; v2(34.45,69.01) 33.73,68.29 R781.2
  L3_INT_1 w0.107: v2(92.74,70.58) 92.33,70.58 92.13,70.39 92.13,70.38 91.9,70.14 86.25,70.14 84.36,68.26 74.73,68.26 73.97,67.5 68.38,67.5 67.9,67.97 65.09,67.97 64.81,67.69 63.01,67.69 61.96,66.65 59.03,66.65 57.71,67.97 36.39,67.97 35.35,69.01 v2(34.45,69.01)
SYS_PGOOD#: length 1.4
  BOTTOM w0.137: R924.2 98.7,69.6 U535.4
SYS_STATUS#: length 52.9
  TOP w0.137: v3(72.62,43) U14.E17 ; U549.7 100.93,64.32 100.91,64.3 v2(100.9,64.3)
  L3_INT_1 w0.107: v2(80.43,55.86) 80.89,55.4 81.37,55.4 81.93,55.97 81.97,55.97 82.15,56.15 82.51,56.15 82.56,56.1 87.77,56.1 88.98,54.89 93.47,54.89 93.83,55.26 93.83,55.84 94.11,56.11 v2(95.59,56.11) ; v2(95.77,64.77) 97.35,64.77 97.83,64.3 v2(100.9,64.3)
  L4_INT_2 w0.107: v3(72.62,43) 72.98,43.35 73.57,43.35 73.57,43.35 74.37,43.35 74.73,43 78.79,43 79.35,43.56 79.35,47.14 79.7,47.49 79.7,49.41 80.35,50.06 80.35,55.38 80.43,55.46 v2(80.43,55.86) ; v2(95.77,64.77) 95.77,64.36 95.83,64.3 95.83,60.92 95.59,60.68 v2(95.59,56.11)
SYS_STATUS_LT#: length 57.9
  TOP w0.137: U549.2 98.2,64.32 98.05,64.18 97.67,64.18 v2(97.23,63.73)
  L3_INT_1 w0.107: v2(97.23,63.73) 97.64,63.73 97.7,63.79 98.51,63.79 99.46,62.84 101.72,62.84 102.54,63.65 104.62,63.65 106.05,62.22 108.89,62.22 v2(109.89,61.22)
  L4_INT_2 w0.107: v2(109.89,61.22) 111.33,62.67 111.33,64.84 112.36,65.87 112.36,78.44 114.44,80.52 114.44,94.68 114.43,94.69 114.43,98.19 v2(115.21,98.97)
  BOTTOM w0.137: v2(115.21,98.97) 115.21,99.7 115.28,99.76 R925.2
TA_BB_RTC: length 35.8
  TOP w0.137: v3(71.83,47.79) 71.43,47.4 U14.F12 ; v2(88.66,57.87) 88.96,57.57 88.98,57.57 89.25,57.31 89.44,57.31 90.77,58.64 U24.4 91.35,57.54 R144.2
  L3_INT_1 w0.107: v2(88.66,57.87) 88.18,58.35 83.33,58.35 82.73,58.95 v2(81.42,58.95)
  L4_INT_2 w0.107: v3(71.83,47.79) 71.44,47.41 71.44,46.84 71.67,46.61 75.18,46.61 75.38,46.81 78.64,46.81 79.46,47.64 79.46,49.51 79.57,49.61 79.57,49.62 80.08,50.13 80.08,55.57 v2(79.79,55.86)
  BOTTOM w0.137: v2(81.42,58.95) 81.12,58.65 81.12,58.64 79.79,57.32 v2(79.79,55.86)
TDI_ANODE: length 36
  TOP w0.137: v2(93.09,56.34) 93.09,56.63 92.32,57.4 92.32,58.27 93.02,58.98 93.33,58.98 C437.2 93.72,59.37 U28.2 ; U14.J13 69.03,46.6 v3(69.43,46.99)
  L3_INT_1 w0.107: v3(69.43,46.99) 69.43,47.26 69.81,47.64 69.81,48.43 69.81,48.44 69.81,48.88 70.73,49.8 72.83,49.8 73.04,50.01 73.04,50.88 73.87,51.71 73.87,51.94 74.08,52.15 74.08,52.15 74.13,52.2 74.4,52.2 75.86,53.67 76.3,53.67 76.63,54
  L3_INT_1 w0.254: 76.63,54 77.5,54.87 77.5,54.93 78,55.43 78.06,55.43 79.37,56.74 81.57,56.74 81.75,56.92 82.83,56.92 82.87,56.87 88.08,56.87 88.09,56.86 89.7,56.86 90.35,56.22 92.4,56.22 92.52,56.34 v2(93.09,56.34)
TDI_CATHODE: length 36
  TOP w0.137: v3(70.23,46.99) 69.83,46.6 U14.H13 ; v2(93.25,55.64) 93.61,55.99 93.61,56.48 92.58,57.51 92.58,58.16 93.13,58.71 93.33,58.71 C437.1 93.79,58.25 94.22,58.25 94.36,58.1 U28.3
  L3_INT_1 w0.107: v3(70.23,46.99) 70.23,47.31 70.37,47.45 70.4,47.45 70.61,47.66 70.61,48.72 70.88,48.99 72.86,48.99 73.85,49.98 73.85,51.11 73.85,51.11 73.85,51.18 74.11,51.44 74.37,51.44 74.58,51.65 74.58,51.84 74.67,51.92 74.67,51.94 75.76,53.03 75.76,53.14 75.97,53.35 76.52,53.35 76.9,53.73
  L3_INT_1 w0.254: 76.9,53.73 77.88,54.71 77.88,54.77 78.16,55.05 78.22,55.05 79.52,56.36 81.81,56.36 81.99,56.54 82.67,56.54 82.72,56.49 87.92,56.49 87.93,56.48 89.54,56.48 90.19,55.84 91.89,55.84 92.09,55.64 v2(93.25,55.64)
TEST_SEL_B: length 52.3
  TOP w0.137: v3(71.82,40.6) U14.F20
  L3_INT_1 w0.107: v2(101.35,55.93) 100.87,55.45 96.31,55.45 95.04,54.18 87.6,54.18 86.67,55.12 84.32,55.12 83.46,54.26 82.16,54.26 v2(81.87,54.55)
  L4_INT_2 w0.107: v3(71.82,40.6) 72.22,40.99 77.44,40.99 79.82,43.36 79.82,46.95 80.16,47.3 80.16,49.22 81.86,50.92 81.86,51.02 81.87,51.03 v2(81.87,54.55)
  BOTTOM w0.137: R157.2 107.63,57.98 J13.2 105.46,57.48 102.28,57.48 101.35,56.56 v2(101.35,55.93)
THERM_FAULT_B: length 40.3
  TOP w0.137: U14.J4 69.42,54.19 v3(69.43,54.19) ; v2(94.1,57.29) 94.16,57.29 94.62,56.83 U28.4
  L3_INT_1 w0.107: v2(94.24,61.88) 91.78,61.88 91.76,61.9 91.75,61.9 89.98,63.68 88.69,63.68 88.11,64.26 77.74,64.26 74.24,60.75 73.46,60.75 72.82,60.11 v2(71.91,60.11)
  L4_INT_2 w0.107: v2(94.1,57.29) 94.1,59.59 94.36,59.85 94.36,61.06 94.24,61.18 v2(94.24,61.88) ; v3(69.43,54.19) 69.84,54.61 70.38,54.61 70.61,54.84 70.61,58.81 v2(71.91,60.11)
  BOTTOM w0.137: R743.1 93.7,57.68 v2(94.1,57.29)
THERM_WARN_B: length 42.9
  TOP w0.137: U28.6 99.67,58.1 99.2,58.57 v2(99.2,60.97) 99.01,61.16 R744.1 ; v3(69.43,54.99) 69.42,54.99 U14.J3
  L3_INT_1 w0.107: v2(71.91,60.8) 73.17,60.8 73.48,61.1 74.25,61.1 77.64,64.49 88.2,64.49 88.78,63.91 93.02,63.91 95.85,61.08 98.45,61.08 98.56,60.97 v2(99.2,60.97)
  L4_INT_2 w0.107: v3(69.43,54.99) 69.96,55.53 69.96,58.84 v2(71.91,60.8)
TMP_DETECT_B: length 21.4
  TOP w0.137: v3(70.22,40.6) U14.H20
  L3_INT_1 w0.107: v3(70.22,40.6) 69.84,40.21 69.84,38.87 70.08,38.64 75.21,38.64 76.3,37.55 84.28,37.55 v2(84.72,37.11)
  BOTTOM w0.137: R158.1 82.92,38.91 v2(84.72,37.11)
U25_IFS: length 10.5
  BOTTOM w0.137: U523.18 20.94,75.2 18.4,77.74 U523.5
UART1_SIN: length 123.8
  TOP w0.137: U14.H2 70.25,55.82 70.25,56.35 70.29,56.39 70.29,60.44 72.3,62.45 v2(74.79,62.45) ; J73.3 127.93,14.39 127.85,14.47 U563.4 127.08,14.47 125.99,15.56 125.99,16.02 125.8,16.21 116.34,16.21 116.15,16.02 115.3,16.02 J72.1
  L3_INT_1 w0.107: v2(74.79,62.45) 75.27,62.45 77.54,64.72 88.3,64.72 88.88,64.14 93.17,64.14 96,61.31 98.97,61.31 99.03,61.38 99.37,61.38 99.59,61.15 103.17,61.15 103.52,61.5 104.12,61.5 104.25,61.37 104.37,61.37 104.77,60.97 107.05,60.97 111.21,56.81 116.22,56.81 118.19,54.84 118.19,45.5 118.9,44.79 118.9,42.43 118.5,42.02 118.5,35.62 120.23,33.89 120.23,30.78 121.97,29.04 121.97,17.65 120.26,15.94 115.22,15.94 J72.1
UART1_SOUT: length 125.7
  TOP w0.137: v2(118.34,12.22) 117.8,12.22 117.59,12.43 R837.1 117.05,12.95 116.38,13.62 116.38,14.81 117.46,15.89 125.07,15.89 126.12,14.84 126.12,14.42 126.1,14.4 126.1,13.04 126.21,12.92 127.34,12.92 U563.1 128.64,12.97 J73.2 ; v2(74.83,63.12) 72.6,63.12 69.82,60.35 U14.H1
  L3_INT_1 w0.107: v2(118.34,12.22) 122.21,16.08 122.21,29.31 120.48,31.03 120.48,33.97 119.47,34.98 119.47,37.97 119.27,38.16 119.27,44.91 118.94,45.24 118.94,48.88 118.53,49.29 118.53,54.83 116.31,57.05 112.31,57.05 108.07,61.28 104.78,61.28 104.47,61.6 104.35,61.6 104.22,61.73 103.42,61.73 103.07,61.39 99.69,61.39 99.47,61.61 98.93,61.61 98.87,61.55 96.1,61.55 93.27,64.38 88.98,64.38 88.4,64.96 77.45,64.96 75.61,63.12 v2(74.83,63.12)
UART2_CTS_B: length 107.5
  TOP w0.137: U14.M2 66.98,55.76 66.98,56.82 66.94,56.86 v2(66.94,63.49)
  L3_INT_1 w0.107: v2(66.94,63.49) 67.23,63.2 69.55,63.2 70.01,63.66 75.75,63.66 75.77,63.66 77.38,65.27 86.61,65.27 86.83,65.5 92.55,65.5 95.58,62.47 97.66,62.47 97.66,62.47 98.02,62.47 98.13,62.37 104.03,62.37 104.88,61.52 108.27,61.52 110.17,59.61 111.64,59.61 112.53,58.72 112.53,58.38 113.52,57.4 116.29,57.4 118.8,54.89 118.8,50.54 119.25,50.09 119.25,45.42 119.51,45.16 119.51,38.26 119.7,38.06 119.7,35.67 120.88,34.5 120.88,31.15 122.57,29.45 122.57,26.2 124.85,23.92 v2(124.85,22.9)
  BOTTOM w0.137: U564.6 v2(124.85,22.9) 124.88,22.87 124.88,21.7 126.12,20.46 J60.6
UART2_RTS_B: length 119.7
  TOP w0.137: J60.2 126.88,27.7 126.88,23.94 125.45,22.51 v2(125.45,21.73) ; U14.L1 67.42,63.87 v2(67.07,64.23)
  L3_INT_1 w0.107: v2(125.45,21.73) 125.95,21.24 126.45,21.24 126.69,21.48 126.69,21.82 126.63,21.88 126.63,23.64 126.82,23.83 126.82,24.78 124.39,27.2 124.39,28.67 123.3,29.77 123.3,31.88 122.02,33.16 122.02,34.44 121.55,34.91 121.55,37.3 121.71,37.47 121.71,41.51 120.59,42.64 120.59,47.1 120.8,47.31 120.87,47.31 122.64,49.09 122.64,50.93 119.8,53.78 119.8,56.71 115.97,60.54 113.98,60.54 112.28,62.25 110.25,62.25 108.92,63.58 106.04,63.58 104.83,64.8 104.23,64.8 104.09,64.94 103.15,65.87 94.94,65.87 93.55,67.27 87.61,67.27 86.32,65.97 75.66,65.97 74.05,64.37 68.18,64.37 68.09,64.46 67.73,64.46 67.49,64.23 v2(67.07,64.23)
  BOTTOM w0.137: U564.5 v2(125.45,21.73)
UART2_SIN: length 103.5
  TOP w0.137: v2(75.74,65.45) 75.4,65.11 73.47,65.11 68.63,60.28 68.63,56.61 U14.K1
  L3_INT_1 w0.107: v2(75.74,65.45) 76.15,65.45 76.21,65.52 76.43,65.74 86.41,65.74 87.67,66.99 93.44,66.99 94.79,65.64 103.05,65.64 104.15,64.53 104.58,64.53 105.87,63.24 108.82,63.24 110.22,61.84 112.02,61.84 114.48,59.38 115.74,59.38 119.5,55.62 119.5,53.65 121.35,51.79 121.35,48.63 120.35,47.63 120.35,42.54 121.48,41.41 121.48,39.09 120.4,38.01 120.4,35.73 121.69,34.44 121.69,33.13 123.07,31.75 123.07,29.67 124.16,28.58 124.16,27.03 126.41,24.79 v2(126.41,24.08)
  BOTTOM w0.137: v2(126.41,24.08) 126.41,24.07 126.28,23.95 U564.1 127.91,23.65 J60.4
UART2_SOUT: length 108.1
  TOP w0.137: U14.L2 67.78,55.76 67.78,56.34 67.73,56.39 67.73,62.69 68.94,63.9 v2(69.59,63.9)
  L3_INT_1 w0.107: v2(69.59,63.9) 75.42,63.9 77.02,65.5 86.51,65.5 87.68,66.68 93.33,66.68 94.59,65.41 102.95,65.41 104.06,64.3 104.33,64.3 105.69,62.93 108.76,62.93 111.04,60.65 112,60.65 112.7,59.95 112.7,59.48 114.27,57.91 116.11,57.91 119.09,54.94 119.09,51.17 120.61,49.65 120.84,49.65 121.12,49.37 121.12,48.97 120.12,47.97 120.12,42.42 121.25,41.29 121.25,39.19 120.17,38.11 120.17,35.54 121.45,34.25 121.45,33.03 122.83,31.65 122.83,29.57 123.93,28.48 123.93,26.94 125.67,25.2 125.67,22.26 v2(126.28,21.65)
  BOTTOM w0.137: v2(126.28,21.65) U564.4 128,22.15 128.85,23 J60.5
UART_PWR2: length 3.1
  BOTTOM w0.137: R920.2 128.21,26.15 129.13,27.07 129.13,27.41 J60.3
UBUS1_AN: length 21.4
  TOP w0.137: U548.8 86.64,111.13 86.55,111.04 85.67,111.04 82.83,108.2 73.93,108.2 73.27,108.85 R401.1
UBUS1_INT: length 72.7
  TOP w0.137: v3(67.83,53.39) 67.82,53.39 U14.L5
  L3_INT_1 w0.107: v2(75.65,72.08) 80.35,76.78 80.35,81.58 85.22,86.45 85.22,89.55 85.17,89.6 85.17,93.43 87.08,95.34 87.08,107.94 v2(90.29,111.15)
  BOTTOM w0.137: v2(90.29,111.15) 90.29,112.02 R869.2 90.8,112.03 90.81,112.04 J57.2 ; v2(75.65,72.08) 75.65,71.12 76.23,70.54 76.23,63.28 74,61.05 73.42,61.05 72.82,60.45 72.82,60.43 72.39,60.01 72.39,58.7 69.8,56.1 69.8,53.24 69.58,53.02 68.2,53.02 v3(67.83,53.39)
UBUS1_PWM: length 7.1
  TOP w0.137: U548.1 88.72,111.13 88.96,111.37 88.96,113.5 90.04,114.58 J57.1
UBUS1_RST: length 64.9
  TOP w0.137: v2(43.86,60.66) R864.2 42.69,61.23 42.18,61.73 42.18,63.62 51.02,72.46 v2(52.08,72.46)
  L3_INT_1 w0.107: v2(52.08,72.46) 52.08,81.42 53.81,83.16 53.81,85.44 58.67,90.3 58.67,92.08 62.02,95.42 62.02,98.02 64.61,100.61 64.61,107.43 J56.2
  BOTTOM w0.137: U546.4 43.74,60.79 v2(43.86,60.66)
UBUS1_SPI_CLK: length 16.4
  TOP w0.137: J56.4 71.05,105.12 74.52,105.12 74.66,105.26 74.66,105.42 74.8,105.56 75.07,105.56 75.21,105.42 75.21,105.26 75.35,105.12 75.62,105.12 75.76,105.26 75.76,105.42 75.9,105.56 76.17,105.56 76.31,105.42 76.31,105.26 76.44,105.12 76.72,105.12 76.86,105.26 76.86,105.42 76.99,105.56 77.27,105.56 77.4,105.42 77.4,105.26 77.54,105.12 78.34,105.12 79.19,104.28 U539.3
UBUS1_SPI_CS0_B: length 18.8
  TOP w0.137: J56.3 72.58,106.14 80.25,106.14 82.29,104.1 U36.3
UBUS1_SPI_MISO: length 16.4
  TOP w0.137: R942.2 75.73,103.98 75.71,104.01 75.71,104.08 75.36,104.42 73.66,104.42 73.53,104.28 73.53,102.88 73.39,102.74 73.11,102.74 72.98,102.88 72.98,104.28 72.84,104.42 72.57,104.42 72.43,104.28 72.43,102.88 72.29,102.74 72.02,102.74 71.88,102.88 71.88,104.28 71.74,104.42 71.47,104.42 71.33,104.28 71.33,102.88 71.19,102.74 70.92,102.74 70.78,102.88 70.78,104.28 70.65,104.42 J56.5
UBUS1_SPI_MOSI: length 16.5
  TOP w0.137: U35.3 73.4,101.42 72.93,101.88 71.16,101.88 71.02,101.74 71.02,96.22 70.88,96.09 70.61,96.09 70.47,96.22 70.47,101.74 70.33,101.88 J56.6
UBUS1_UART_SIN: length 64.2
  TOP w0.137: U14.J1 69.02,60.29 73.38,64.65 75.54,64.65 76.23,65.34 76.23,68.77 76.15,68.85 v2(76.15,71.69)
  L3_INT_1 w0.107: v2(76.15,71.69) 76.15,72.1 84.71,80.66 84.71,85.61 85.45,86.35 85.45,89.8 85.4,89.85 85.4,92.95 87.62,95.17 87.62,105.04 J57.3
UBUS1_UART_SOUT: length 62.4
  TOP w0.137: v2(76.79,71.66) 76.79,65.53 75.65,64.38 73.49,64.38 69.38,60.28 69.38,55.76 U14.J2
  L3_INT_1 w0.107: J57.4 88.1,102.98 88.1,94.94 86.68,93.51 86.68,90.21 86.01,89.55 86.01,86.59 85.1,85.67 85.1,80.44 76.79,72.12 v2(76.79,71.66)
USB1_DRVVBUS: length 73.2
  TOP w0.137: U40.A1 v2(111.99,91.32) ; v3(70.23,52.6) 70.22,52.6 U14.H6
  L3_INT_1 w0.107: v2(106.26,78.1) 102.57,78.1 101.2,76.72 89.87,76.72 v2(89.06,77.54)
  L4_INT_2 w0.107: v2(106.26,78.1) 106.26,83.9 111.99,89.63 v2(111.99,91.32)
  BOTTOM w0.137: v3(70.23,52.6) 70.65,53.02 70.65,56.58 72.66,58.59 72.66,59.9 73.08,60.32 73.08,60.34 73.53,60.79 74.11,60.79 76.65,63.33 76.65,70.68 80.68,74.71 80.68,76.04 82.18,77.54 v2(89.06,77.54) ; v2(111.99,91.32) 111.99,90.9 111.95,90.86 R242.1
USB1_ID: length 14.1
  TOP w0.137: U14.F5 v3(71.07,52.64)
  L4_INT_2 w0.107: v2(73.87,61.56) 73.87,59.52 73.44,59.09 73.44,53.68 72.77,53 71.64,53 71.27,52.64 v3(71.07,52.64)
  BOTTOM w0.137: R248.1 74.65,63.6 73.87,62.82 v2(73.87,61.56)
USB1_ILIM: length 1.3
  TOP w0.137: R243.1 110.4,91.84 110.44,91.87 U40.A3
USB1_ISO_VOUT: length 3.2
  L3_INT_1 w0.488: J70.1 108.73,107.27 ; J70.1 107.17,107.27 ; J70.1 107.95,108.04
  BOTTOM w0.305: U42.4 v4(105.2,110.98)
  vias: v5(110.4,99.05) v5(110.93,99.94) v5(111.41,99.23)
USB1_PWRFAULT: length 59.5
  TOP w0.137: U530.4 100.01,85.23 v2(100.7,84.55) ; U14.G6 70.28,51.85 70.28,51.84 v3(70.27,51.84)
  L3_INT_1 w0.107: v2(86.89,84.55) 87.39,85.06 100.18,85.06 v2(100.7,84.55)
  L4_INT_2 w0.107: v3(70.27,51.84) 70.62,52.19 70.62,52.7 70.96,53.04 71.29,53.04 71.61,53.36 72.33,53.36 72.64,53.66 72.64,58.82 73.45,59.63 v2(73.45,60.11) ; v2(86.89,84.55) 86.89,76.98 v2(87.33,76.53)
  BOTTOM w0.137: v2(87.33,76.53) 85.54,76.53 82.79,73.78 82.17,73.78 76.95,68.56 76.95,63.18 73.88,60.11 v2(73.45,60.11) ; R793.1 v2(100.7,84.55)
USB1_RESREF: length 10.1
  TOP w0.137: v3(71.03,55) 70.63,54.6 U14.G3
  L4_INT_2 w0.107: v2(71.96,61.51) 72.32,61.15 72.32,59.91 71.03,58.62 v3(71.03,55)
  BOTTOM w0.137: R249.1 71.96,63.36 71.96,63.35 v2(71.96,61.51)
USB1_RX_N: length 70
  BOTTOM w0.132: J70.5 100.44,105.46 arc(100.51,105.32) 100.66,105.27 arc(100.85,105.33) 101.01,105.45 arc(101.13,105.64) 101.24,105.84 101.79,106.98 arc(101.84,107.51) 101.52,107.94 arc(100.7,108.14) 99.93,107.81 arc(99.31,107.33) 98.62,106.98 arc(97.68,106.42) 96.92,105.63 96.33,104.8 arc(96.05,104.28) 95.92,103.69 95.73,101.45 arc(95.59,99.34) 95.55,97.23 95.55,96.82 arc(95.58,96.47) U44.7 U44.4 arc(95.58,94.93) 95.55,94.62 arc(95.56,94.06) 95.53,93.49 94.87,86.11 arc(94.72,85.53) 94.39,85.02 93.7,84.26 arc(93.26,83.68) 92.93,83.03 arc(92.28,80.99) 91.95,78.87 91.77,76.67 arc(91.27,74.76) 90.14,73.14 72.97,55.97 arc(72.91,55.87) 72.88,55.76 72.88,55.3 arc(72.86,55.16) 72.78,55.05 arc(72.67,54.88) 72.63,54.69 72.63,54.61 arc(72.63,54.6) 72.63,54.58 72.63,54.58 arc(72.6,54.42) 72.51,54.28 72.37,54.13 arc(72.26,53.98) v1(72.23,53.8)
USB1_RX_P: length 70
  BOTTOM w0.132: J70.6 102.27,105.69 arc(102.09,105.65) 101.92,105.7 arc(101.77,105.81) 101.69,105.98 arc(101.67,106.06) 101.69,106.15 102.02,106.84 arc(102.09,107.56) 101.65,108.15 arc(100.68,108.39) 99.76,107.99 arc(99.18,107.54) 98.53,107.21 arc(97.53,106.62) 96.72,105.77 96.13,104.95 arc(95.82,104.36) 95.68,103.71 95.48,101.47 arc(95.35,99.35) 95.3,97.23 95.3,96.82 arc(95.27,96.47) U44.6 U44.5 arc(95.27,94.92) 95.31,94.61 arc(95.31,94.06) 95.28,93.51 94.62,86.13 arc(94.49,85.63) 94.2,85.18 93.52,84.42 arc(93.05,83.81) 92.7,83.12 arc(92.04,81.05) 91.7,78.89 91.52,76.69 arc(91.04,74.86) 89.96,73.31 73.84,57.19 arc(73.71,57.14) 73.59,57.19 73.5,57.28 arc(73.44,57.32) 73.38,57.34 arc(73.27,57.34) 73.16,57.3 73.15,57.28 arc(73.14,57.28) 73.13,57.27 73.12,57.26 arc(73.03,57.1) 73.1,56.93 73.21,56.81 arc(73.27,56.69) 73.21,56.56 72.8,56.14 arc(72.68,55.97) 72.64,55.76 72.64,55.43 arc(72.6,55.26) 72.51,55.12 72.31,54.92 arc(72.25,54.83) 72.23,54.72 v1(72.23,54.6)
USB1_TX_N: length 54.7
  TOP w0.132: U14.F2 71.18,55.64 arc(71.08,55.79) 71.05,55.96 71.05,56.26 arc(71.06,56.33) 71.1,56.38 arc(71.15,56.47) 71.17,56.57 71.17,56.93 arc(71.33,57.68) 71.82,58.28 87.37,69.78 arc(88.26,70.61) 88.94,71.64 96.34,86.13 arc(97.05,88.03) 97.29,90.04 97.29,92.52 arc(97.73,93.6) 98.81,94.04 100.81,94.04 arc(101.26,93.86) 101.45,93.41 101.45,93.2 arc(101.47,93.08) 101.54,92.97 v2(101.71,92.8)
  BOTTOM w0.132: v2(101.71,92.8) C463.2
USB1_TX_P: length 54.6
  TOP w0.132: v2(100.98,92.8) 101.08,92.9 arc(101.17,93.04) 101.2,93.2 101.2,93.41 arc(101.09,93.68) 100.81,93.79 98.81,93.79 arc(97.91,93.42) 97.54,92.52 97.54,90.04 arc(97.29,87.97) 96.56,86.02 89.16,71.52 arc(88.45,70.45) 87.51,69.58 76.01,61.07 arc(75.94,60.95) 75.97,60.81 arc(76,60.68) 75.93,60.56 75.8,60.46 arc(75.67,60.43) 75.55,60.5 arc(75.43,60.57) 75.29,60.54 75.16,60.44 arc(75.09,60.32) 75.12,60.18 arc(75.16,60.05) 75.08,59.93 74.95,59.83 arc(74.82,59.8) 74.7,59.87 arc(74.58,59.94) 74.44,59.91 74.31,59.81 arc(74.24,59.69) 74.27,59.55 arc(74.31,59.42) 74.23,59.3 74.1,59.2 arc(73.97,59.17) 73.85,59.24 arc(73.73,59.31) 73.59,59.28 73.46,59.18 arc(73.39,59.06) 73.42,58.93 73.42,58.93 arc(73.46,58.79) 73.38,58.67 73.25,58.57 arc(73.12,58.54) 73,58.61 arc(72.88,58.68) 72.74,58.65 71.97,58.08 arc(71.55,57.57) 71.42,56.93 71.42,56.2 arc(71.42,56.2) U14.F1
  BOTTOM w0.132: v2(100.98,92.8) C464.2
USB1_UDM: length 88.8
  TOP w0.132: U14.E6 72.23,52.2 v3(72.63,52.6)
  BOTTOM w0.132: v3(72.63,52.6) 72.54,52.6 72.13,52.19 71.61,52.19 71.44,52.36 71.44,56.86 90.13,75.55 90.13,82.61 93.54,86.01 93.54,94.76 94.09,95.31 94.09,104.66 95.55,106.13 95.55,110 100.13,114.57 103.16,114.57 103.41,114.33 103.41,113.87 103.53,113.77 103.84,113.78 104.34,113.28 U42.3 104.34,112.47 103.45,111.59 103.45,109.92 104.6,108.77 104.6,107.35 104.69,107.27 J70.2
USB1_UDP: length 88.7
  TOP w0.132: v3(71.83,52.6) 71.43,52.2 U14.F6
  BOTTOM w0.132: v3(71.83,52.6) 71.83,52.97 71.68,53.11 71.68,56.72 73.4,58.43 73.59,58.43 73.78,58.24 73.97,58.24 74.16,58.42 74.16,58.61 73.96,58.81 73.96,58.99 74.15,59.18 74.33,59.18 74.53,58.98 74.72,58.98 74.9,59.17 74.9,59.36 74.71,59.56 74.71,59.74 74.89,59.93 75.08,59.93 75.28,59.73 75.46,59.73 75.65,59.92 75.65,60.11 75.45,60.3 75.45,60.49 90.38,75.41 90.38,82.5 93.78,85.91 93.78,94.66 94.33,95.21 94.33,104.56 95.8,106.03 95.8,109.9 100.23,114.33 103.06,114.33 103.17,114.22 103.17,113.85 103.08,113.76 102.6,113.74 102.34,113.47 U42.2 102.34,112.5 103.21,111.62 103.21,109.82 104.36,108.67 104.36,107.4 104.22,107.27 J70.3
USB2_DRVVBUS: length 15
  TOP w0.137: U550.A1 v2(105.29,91.02) ; U554.6 102.8,82.77 v2(103.11,83.08)
  L4_INT_2 w0.107: v2(105.29,91.02) 104.23,89.96 104.23,88.8 104.17,88.74 104.17,84.8 103.11,83.73 v2(103.11,83.08)
  BOTTOM w0.137: v2(105.29,91.02) 105.29,90.71 105.29,90.7 R882.1
USB2_DRVVBUS_I2C3_SCL: length 61.2
  TOP w0.137: U554.2 102.79,77.26 102.79,76.18 v2(102.62,76.01) ; U14.L4 67.82,54.19 v3(67.83,54.19)
  L3_INT_1 w0.107: v2(102.62,76.01) 95.39,76.01 92.82,73.44 81.15,73.44 78.57,70.86 75.62,70.86 74.56,71.92 74.2,71.92 72.99,70.71 66.39,70.71 v2(66.18,70.92)
  BOTTOM w0.137: v3(67.83,54.19) 67.83,54.57 67.83,54.57 67.83,55.02 67.91,55.1 67.91,56.25 70.4,58.74 70.4,65.67 66.04,70.03 66.04,70.41 66.18,70.54 v2(66.18,70.92)
USB2_ID: length 9.6
  TOP w0.137: U14.D5 73.42,53.4 73.42,54.76 73.68,55.01 74.75,55.01 75.05,55.31 75.05,55.72 77.46,58.13 R883.1
USB2_ILIM: length 1.4
  TOP w0.137: U550.A3 103.66,91.57 103.65,91.56 R881.1
USB2_ISO_VOUT: length 2.3
  TOP w0.518: 107.17,104.07 J70.10 ; J70.10 108.73,104.07 ; J70.10 107.95,104.84
  BOTTOM w0.381: 104.81,97.99 C1324.1
  vias: v5(103.9,98.71) v5(104.7,98.87) v5(105.07,99.6)
USB2_PWRFAULT: length 13.4
  TOP w0.137: v2(103.82,88.97) 103.82,88.94 103.94,88.83 U551.4 ; U554.7 102.4,83.66 v2(102.71,83.96)
  L4_INT_2 w0.107: v2(102.71,83.96) 103,84.25 103.01,84.25 103.82,85.06 v2(103.82,88.97)
  BOTTOM w0.137: R880.1 104,88.35 103.82,88.52 v2(103.82,88.97)
USB2_PWRFAULT_I2C3_SDA: length 63
  TOP w0.137: v2(102.14,76.53) 102.4,76.79 U554.1 ; U14.M4 v3(66.19,53.37)
  L3_INT_1 w0.107: v2(102.14,76.53) 101.98,76.37 95.24,76.37 92.67,73.8 81,73.8 78.42,71.23 75.77,71.23 74.71,72.28 74.05,72.28 72.84,71.07 66.61,71.07 66.35,71.33 66.01,71.33 65.75,71.07 65.69,71.07 v2(65.53,70.92)
  BOTTOM w0.137: v3(66.19,53.37) 67,53.37 67.44,53.8 67.44,54.73 67.44,54.73 67.44,55.18 67.52,55.26 67.52,56.41 70.01,58.9 70.01,65.51 65.65,69.86 65.65,70.38 65.53,70.5 v2(65.53,70.92)
USB2_RESREF: length 11
  TOP w0.137: v3(71.03,54.19) 70.63,53.8 U14.G4
  L4_INT_2 w0.107: v3(71.03,54.19) 71.38,54.55 71.38,58.54 72.71,59.86 72.71,61.47 v2(72.71,61.57)
  BOTTOM w0.137: R257.1 72.92,63.36 72.71,63.15 v2(72.71,61.57)
USB2_RX_N: length 61.6
  BOTTOM w0.132: v1(73.83,53.8) 73.55,54.08 arc(73.45,54.22) 73.42,54.38 73.41,54.46 arc(73.42,54.5) 73.42,54.55 arc(73.42,54.57) 73.42,54.6 arc(73.43,54.66) 73.45,54.72 arc(73.53,54.86) 73.66,54.95 arc(73.79,55.03) 73.91,55.13 arc(74.03,55.21) 74.17,55.24 74.6,55.24 arc(74.62,55.24) 74.65,55.24 74.96,55.24 arc(75.08,55.26) 75.18,55.33 arc(75.24,55.42) 75.27,55.54 75.27,56.92 arc(75.33,57.24) 75.51,57.51 89.47,71.52 arc(89.52,71.56) 89.56,71.61 92.3,74.67 arc(92.38,74.76) 92.46,74.84 arc(92.98,75.7) 93.17,76.68 93.21,76.71 93.21,80.03 arc(93.55,81.69) 94.52,83.08 95.83,84.32 arc(96,84.54) 96.09,84.81 arc(96.62,89.69) 96.75,94.6 arc(96.75,94.63) 96.75,94.67 U44.2 U44.9 96.67,96.59 arc(96.68,96.64) 96.71,96.68 96.76,96.73 arc(96.79,96.77) 96.8,96.82 96.8,96.95 arc(97.19,98.7) 98.27,100.13 arc(99.21,100.77) 100.27,101.18 arc(100.6,101.32) 100.87,101.53 101.17,101.82 arc(101.3,102.04) 101.33,102.3 101.33,102.44 arc(101.29,102.53) 101.19,102.57 J70.14
